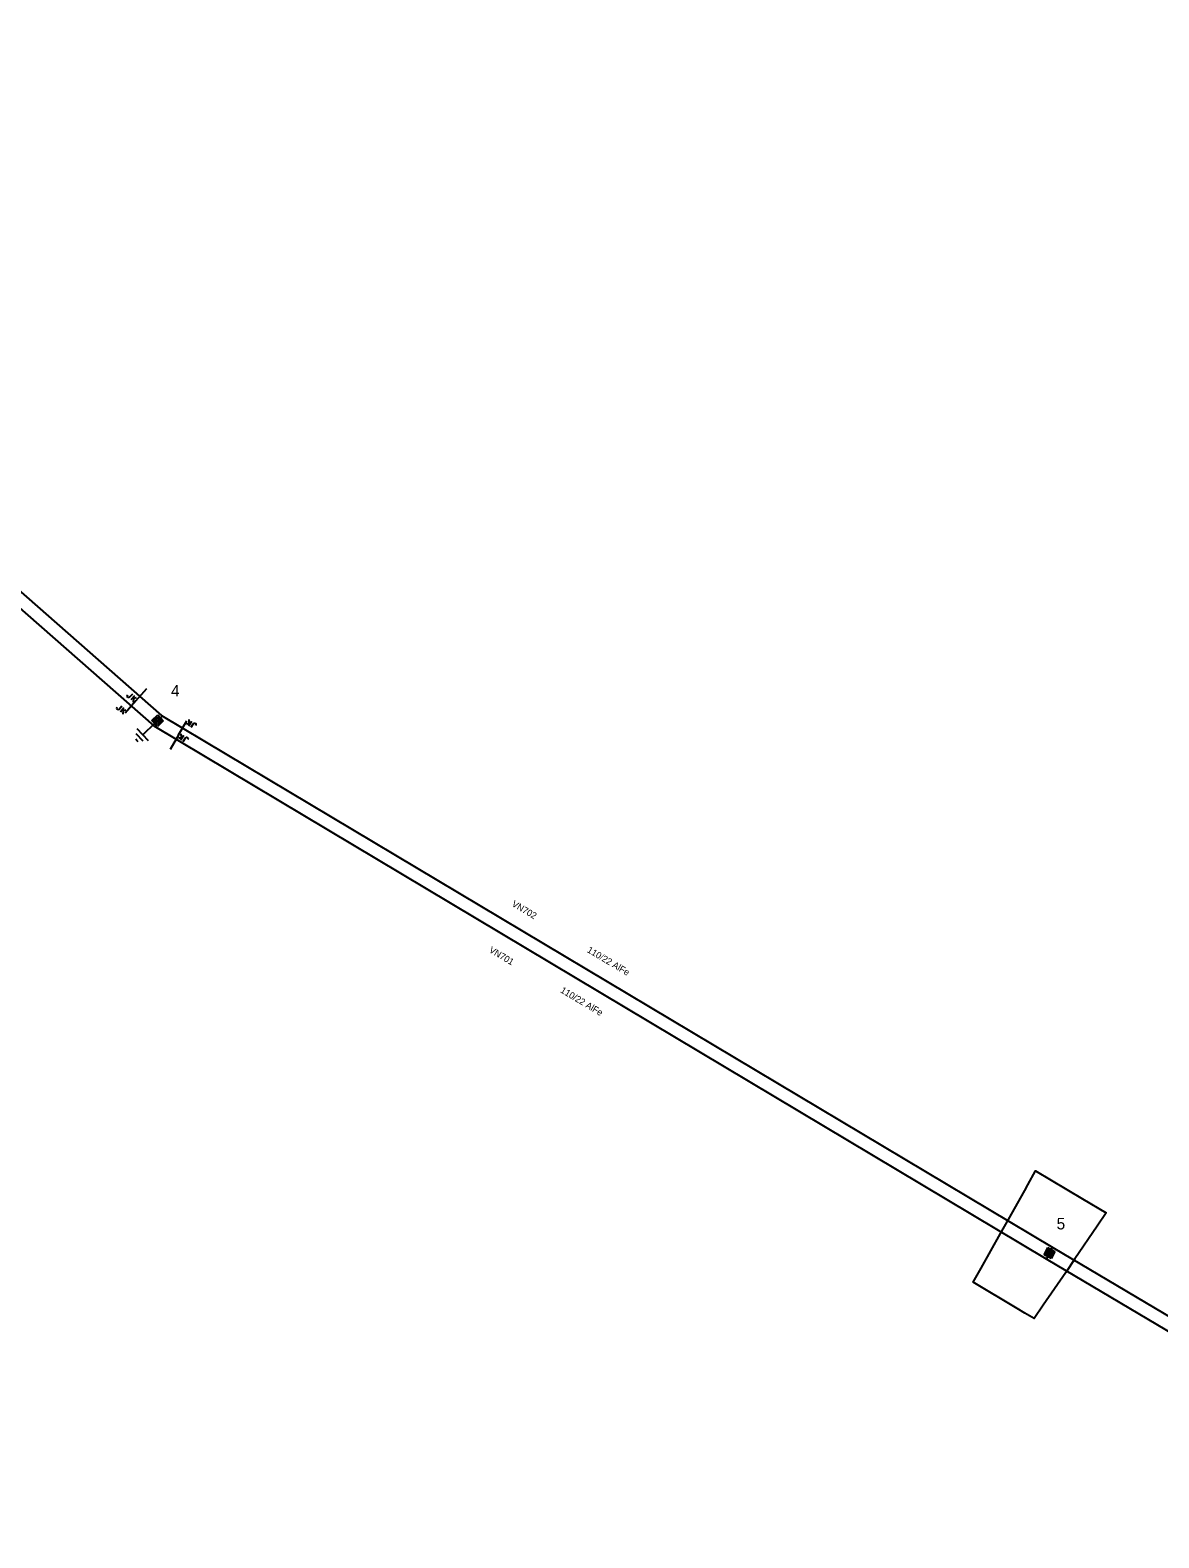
# Model space of a CAD drawing. Extents: x -545588 to -543214, y -1196037 to -1194452.
# Drawn here: x -544989.1 to -544817.1, y -1195194.1 to -1194964.4 of the extents above; entities that cross this region are included whole.
import ezdxf

# ---------------------------------------------------------------- set-up
doc = ezdxf.new("R2010")
doc.units = 0
for name, color, linetype in [('DOPLŇ_POPISY', 7, 'Continuous'), ('ELE_EON_POPIS', 7, 'Continuous'), ('Implicitní', 7, 'Continuous'), ('POL_ZNAČKA_PRACOVNÍ', 7, 'Continuous'), ('SDEL_EON', 7, 'Continuous'), ('Vrstva 18', 7, 'Continuous'), ('Vrstva 35', 7, 'Continuous')]:
    doc.layers.add(name, color=color, linetype=linetype)

# ---------------------------------------------------------------- blocks, each defined once
blk = doc.blocks.new('VN840')
at = {"layer": 'POL_ZNAČKA_PRACOVNÍ'}
for points in [[(-0.01, 1.41), (-0.01, -1.09)], [(-1.51, -1.24), (-1.51, -1.15)], [(-1.48, -1.35), (-1.51, -1.24)], [(-1.33, -1.42), (-1.48, -1.35)], [(-1.27, -1.42), (-1.33, -1.42)], [(-1.13, -1.35), (-1.27, -1.42)], [(-1.09, -1.24), (-1.13, -1.35)], [(-1.09, -0.59), (-1.09, -1.24)], [(-0.68, -0.59), (-0.68, -1.42)], [(-0.68, -1.11), (-0.27, -0.59)], [(-0.54, -0.94), (-0.2, -1.42)]]:
    blk.add_lwpolyline(points, dxfattribs=at)
blk = doc.blocks.new('VN810')
at = {"layer": 'POL_ZNAČKA_PRACOVNÍ'}
for points in [[(0, -1.25), (0, -3.75)], [(1.25, -3.75), (-1.25, -3.75)], [(0.77, -4.37), (-0.8, -4.37)], [(0, -5), (-0.25, -5)], [(0.27, -5), (0, -5)]]:
    blk.add_lwpolyline(points, dxfattribs=at)
blk = doc.blocks.new('VN470')
at = {"layer": 'ELE_EON_POPIS'}
for points in [[(-1.23, 1.22), (1.23, 1.22)], [(-1.23, -1.23), (-1.23, 1.22)], [(-0.92, 0.9), (0.92, 0.9)], [(-0.92, -0.95), (-0.92, 0.9)], [(-0.61, 0.61), (0.61, 0.61)], [(-0.61, -0.62), (-0.61, 0.61)], [(-0.31, -0.27), (-0.31, 0.34)], [(-0.31, 0.34), (0.31, 0.34)], [(0, 1.22), (0, 1.97)], [(0.31, 0.34), (0.31, -0.27)], [(0.61, 0.61), (0.61, -0.62)], [(0.92, 0.9), (0.92, -0.95)], [(1.23, 1.22), (1.23, -1.23)], [(1.23, -1.23), (-1.23, -1.23)], [(0.92, -0.95), (-0.92, -0.95)], [(0.61, -0.62), (-0.61, -0.62)], [(0.31, -0.27), (-0.31, -0.27)], [(0, -1.23), (0, -1.98)]]:
    blk.add_lwpolyline(points, dxfattribs=at)

msp = doc.modelspace()

# ---------------------------------------------------------------- linework, layer by layer
at = {"layer": 'Implicitní'}
for points in [[(-545087.92, -1194964.41), (-544969.06, -1195068.81), (-544833.21, -1195149.88), (-544688.64, -1195235.58), (-544556.54, -1195314.1), (-544420.62, -1195395.04), (-544280.05, -1195478.05), (-544140.98, -1195560.03), (-544005.82, -1195639.79), (-543873.77, -1195718.4), (-543750.46, -1195791.32), (-543648.45, -1195852.42)], [(-545089.24, -1194965.91), (-544970.24, -1195070.43), (-544834.23, -1195151.6), (-544689.66, -1195237.3), (-544557.56, -1195315.82), (-544421.64, -1195396.76), (-544281.07, -1195479.77), (-544142, -1195561.75), (-544006.84, -1195641.51), (-543874.79, -1195720.12), (-543751.48, -1195793.04), (-543649.47, -1195854.14)]]:
    msp.add_lwpolyline(points, dxfattribs=at)
at = {"layer": 'Vrstva 35'}
msp.add_lwpolyline([(-544838.62, -1195159.2), (-544845.35, -1195155.18), (-544844.15, -1195153.03), (-544841.19, -1195147.77), (-544839.99, -1195145.61), (-544837.5, -1195141.19), (-544837.03, -1195140.35), (-544835.83, -1195138.2), (-544828.69, -1195142.46), (-544825.06, -1195144.61), (-544826.45, -1195146.65), (-544829.86, -1195151.64), (-544831.25, -1195153.68), (-544834.67, -1195158.68), (-544836.06, -1195160.72), (-544837.5, -1195159.87)], close=True, dxfattribs=at)

# ---------------------------------------------------------------- block references
at = {"layer": 'DOPLŇ_POPISY'}
for p, xscale, yscale, rotation in [((-544969.65, -1195069.62), 0.49999999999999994, 0.5000000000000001, 133.64068136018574), ((-544833.72, -1195150.74), 0.4999999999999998, 0.5, 152.53911109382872)]:
    msp.add_blockref('VN470', p, dxfattribs=dict(at, xscale=xscale, yscale=yscale, rotation=rotation))
at = {"layer": 'POL_ZNAČKA_PRACOVNÍ', "rotation": -46.35931863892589}
msp.add_blockref('VN810', (-544969.19, -1195069.18), dxfattribs=at)
at = {"layer": 'Vrstva 18'}
for p, rotation in [((-544972.28, -1195065.84), -41.32799999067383), ((-544973.87, -1195067.68), -41.31261387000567), ((-544965.76, -1195070.56), 149.13918058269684), ((-544966.97, -1195072.72), 149.147380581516)]:
    msp.add_blockref('VN840', p, dxfattribs=dict(at, rotation=rotation))

# ---------------------------------------------------------------- texts
at = {"layer": 'ELE_EON_POPIS'}
for rotation, p in [(329.172, (-544904.28, -1195104.83)), (329.176, (-544908.35, -1195110.96))]:
    msp.add_text('110/22 AlFe', height=1, rotation=rotation, dxfattribs=at).set_placement(p)
at = {"layer": 'POL_ZNAČKA_PRACOVNÍ'}
for s, p in [('4', (-544967.6, -1195065.93)), ('5', (-544832.63, -1195147.13))]:
    msp.add_text(s, height=1.75, dxfattribs=at).set_placement(p)
at = {"layer": 'SDEL_EON'}
for s, rotation, p in [('VN702', 329.172, (-544915.76, -1195097.81)), ('VN701', 329.176, (-544919.22, -1195104.83))]:
    msp.add_text(s, height=1, rotation=rotation, dxfattribs=at).set_placement(p)

doc.saveas('drawing.dxf')
